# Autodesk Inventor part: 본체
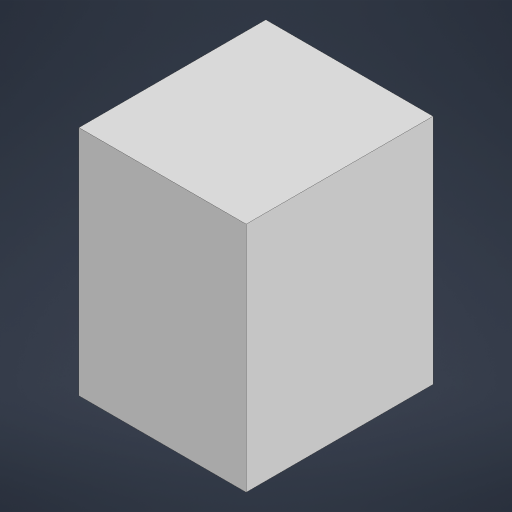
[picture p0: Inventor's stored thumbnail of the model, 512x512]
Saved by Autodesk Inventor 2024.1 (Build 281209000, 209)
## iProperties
Created: 2024-02
Part Number: 본체
Material: 일반
Document SubType Name: Modeling
Designer: mdu
Density: 1 g/cm^3
Appearance: 기본값
Author: mdu
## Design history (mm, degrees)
sketch "스케치1"
  geometry: L1 (0.294, -0.274)-(-6.908, -0.274); L2 (-6.908, -0.274)-(-6.908, -8.321); L3 (-6.908, -8.321)-(0.294, -8.321); L4 (0.294, -8.321)-(0.294, -0.274); 1 further point
  constraints: 8 end point, 2 parallel, 1 horizontal, 1 perpendicular
extrude "돌출1" new body sketch "스케치1" distance "d0" = 10; taper "d1" = 0 deg
node "솔리드1"
